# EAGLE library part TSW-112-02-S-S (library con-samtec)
THROUGH-HOLE .025" SQ POST HEADER Source: Samtec TSW.pdf
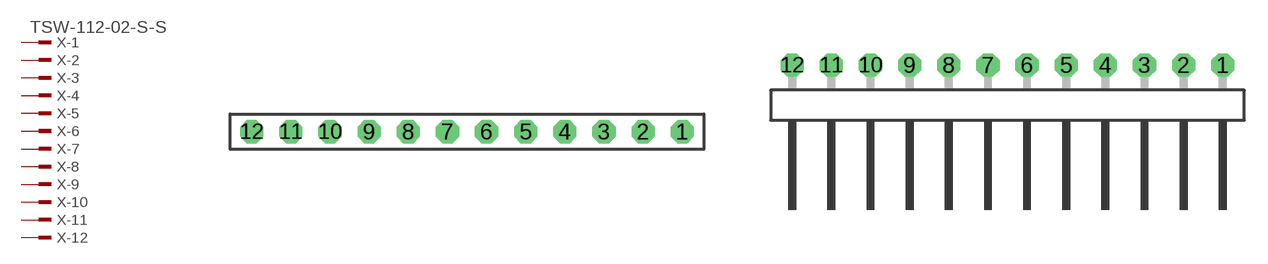
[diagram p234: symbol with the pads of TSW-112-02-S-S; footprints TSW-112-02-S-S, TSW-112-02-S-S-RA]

Designator prefix X; gates -1=MPINV -2=MPIN -3=MPIN -4=MPIN -5=MPIN -6=MPIN -7=MPIN -8=MPIN -9=MPIN -10=MPIN -11=MPIN -12=MPIN

## TSW-112-02-S-S (OC_FARNELL: unknown; OC_NEWARK: unknown)  [TSW-112-02-S-S]
1  -1:1  pas
2  -2:1  pas
3  -3:1  pas
4  -4:1  pas
5  -5:1  pas
6  -6:1  pas
7  -7:1  pas
8  -8:1  pas
9  -9:1  pas
10  -10:1  pas
11  -11:1  pas
12  -12:1  pas

## TSW-112-02-S-S-RA (OC_FARNELL: unknown; OC_NEWARK: unknown)  [TSW-112-02-S-S-RA]
Pads as for TSW-112-02-S-S

## Footprint TSW-112-02-S-S (pad centres in mm)
THROUGH-HOLE .025" SQ POST HEADER Source: Samtec TSW.pdf
drill 1 pad 1.5 octagon: 1 13.97,0; 2 11.43,0; 3 8.89,0; 4 6.35,0; 5 3.81,0; 6 1.27,0; 7 -1.27,0; 8 -3.81,0; 9 -6.35,0; 10 -8.89,0; 11 -11.43,0; 12 -13.97,0

## Footprint TSW-112-02-S-S-RA (pad centres in mm)
THROUGH-HOLE .025" SQ POST HEADER Source: Samtec TSW.pdf
drill 1 pad 1.5 octagon: 1 13.97,1.524; 2 11.43,1.524; 3 8.89,1.524; 4 6.35,1.524; 5 3.81,1.524; 6 1.27,1.524; 7 -1.27,1.524; 8 -3.81,1.524; 9 -6.35,1.524; 10 -8.89,1.524; 11 -11.43,1.524; 12 -13.97,1.524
